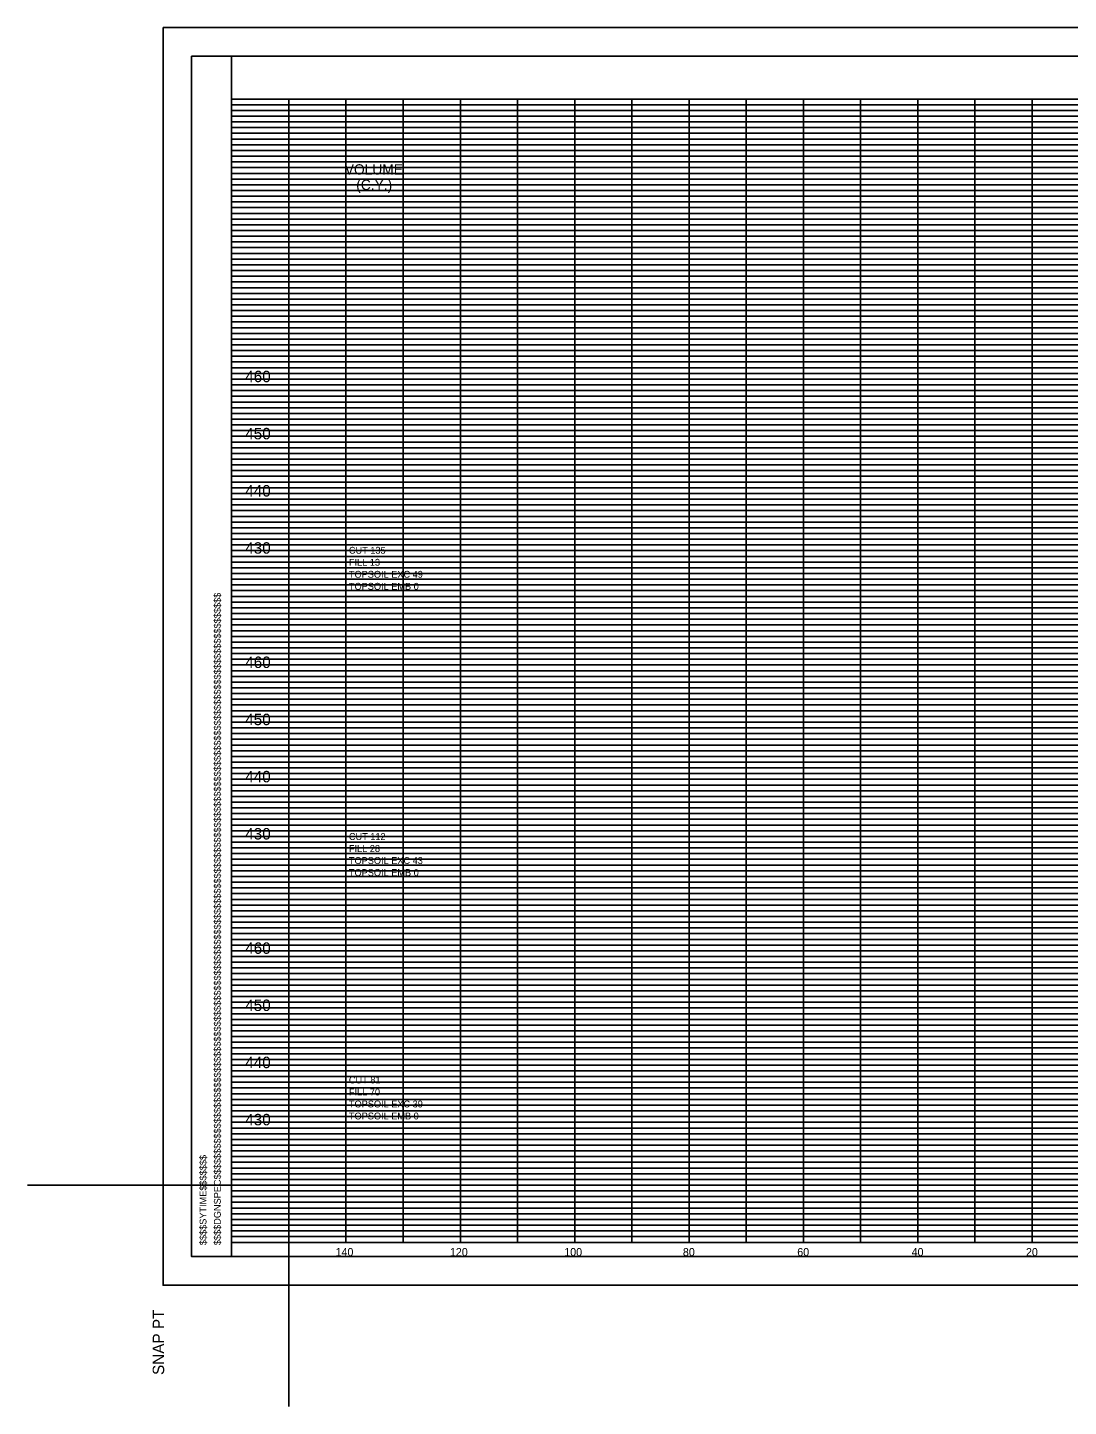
# Model space of a CAD drawing. Extents: x 37 to 1710, y 707 to 2305.
# Drawn here: x 1344.3 to 1526.3, y 971.3 to 1212.5 of the extents above; entities that cross this region are included whole.
import ezdxf

# ---------------------------------------------------------------- set-up
doc = ezdxf.new("R2010")
doc.units = 0
for name, color, linetype in [('DESIGN - SCRATCH - User 1', 7, 'Continuous'), ('DESIGN - SHEET - Corner Text', 7, 'Continuous'), ('DESIGN - SHEET - Light Grid', 7, 'Continuous'), ('DESIGN - SHEET - Linework', 7, 'Continuous'), ('DESIGN - SHEET - Plot Shape', 7, 'Continuous'), ('DESIGN - TYPICAL - Text', 7, 'Continuous')]:
    doc.layers.add(name, color=color, linetype=linetype)

msp = doc.modelspace()

# ---------------------------------------------------------------- linework, layer by layer
at = {"layer": 'DESIGN - SCRATCH - User 1'}
for p, q in [((1390, 1010), (1344.31, 1010)), ((1390, 1010), (1390, 971.3)), ((1380, 1000), (1380, 1000))]:
    msp.add_line(p, q, dxfattribs=at)
at = {"layer": 'DESIGN - SHEET - Light Grid'}
for p, q in [((1380, 1199), (1660, 1199)), ((1380, 1198), (1660, 1198)), ((1380, 1197), (1660, 1197)), ((1380, 1196), (1660, 1196)), ((1380, 1195), (1660, 1195)), ((1380, 1194), (1660, 1194)), ((1380, 1193), (1660, 1193)), ((1380, 1192), (1660, 1192)), ((1380, 1191), (1660, 1191)), ((1380, 1189), (1700, 1189)), ((1380, 1188), (1700, 1188)), ((1380, 1187), (1700, 1187)), ((1380, 1186), (1700, 1186)), ((1380, 1185), (1700, 1185)), ((1380, 1184), (1700, 1184)), ((1380, 1183), (1700, 1183)), ((1380, 1182), (1700, 1182)), ((1380, 1181), (1700, 1181)), ((1380, 1179), (1700, 1179)), ((1380, 1178), (1700, 1178)), ((1380, 1177), (1700, 1177)), ((1380, 1176), (1700, 1176)), ((1380, 1175), (1700, 1175)), ((1380, 1174), (1700, 1174)), ((1380, 1173), (1700, 1173)), ((1380, 1172), (1700, 1172)), ((1380, 1171), (1700, 1171)), ((1380, 1169), (1700, 1169)), ((1380, 1168), (1700, 1168)), ((1380, 1167), (1700, 1167)), ((1380, 1166), (1700, 1166)), ((1380, 1165), (1700, 1165)), ((1380, 1164), (1700, 1164)), ((1380, 1163), (1700, 1163)), ((1380, 1162), (1700, 1162)), ((1380, 1161), (1700, 1161)), ((1380, 1159), (1700, 1159)), ((1380, 1158), (1700, 1158)), ((1380, 1157), (1700, 1157)), ((1380, 1156), (1700, 1156)), ((1380, 1155), (1700, 1155)), ((1380, 1154), (1700, 1154)), ((1380, 1153), (1700, 1153)), ((1380, 1152), (1700, 1152)), ((1380, 1151), (1700, 1151)), ((1380, 1149), (1700, 1149)), ((1380, 1148), (1700, 1148)), ((1380, 1147), (1700, 1147)), ((1380, 1146), (1700, 1146)), ((1380, 1145), (1700, 1145)), ((1380, 1144), (1700, 1144)), ((1380, 1143), (1700, 1143)), ((1380, 1142), (1700, 1142)), ((1380, 1141), (1700, 1141)), ((1380, 1139), (1700, 1139)), ((1380, 1138), (1700, 1138)), ((1380, 1137), (1700, 1137)), ((1380, 1136), (1700, 1136)), ((1380, 1135), (1700, 1135)), ((1380, 1134), (1700, 1134)), ((1380, 1133), (1700, 1133)), ((1380, 1132), (1700, 1132)), ((1380, 1131), (1700, 1131)), ((1380, 1129), (1700, 1129)), ((1380, 1128), (1700, 1128)), ((1380, 1127), (1700, 1127)), ((1380, 1126), (1700, 1126)), ((1380, 1125), (1700, 1125)), ((1380, 1124), (1700, 1124)), ((1380, 1123), (1700, 1123)), ((1380, 1122), (1700, 1122)), ((1380, 1121), (1700, 1121)), ((1380, 1119), (1700, 1119)), ((1380, 1118), (1700, 1118)), ((1380, 1117), (1700, 1117)), ((1380, 1116), (1700, 1116)), ((1380, 1115), (1700, 1115)), ((1380, 1114), (1700, 1114)), ((1380, 1113), (1700, 1113)), ((1380, 1112), (1700, 1112)), ((1380, 1111), (1700, 1111)), ((1380, 1109), (1700, 1109)), ((1380, 1108), (1700, 1108)), ((1380, 1107), (1700, 1107)), ((1380, 1106), (1700, 1106)), ((1380, 1105), (1700, 1105)), ((1380, 1104), (1700, 1104)), ((1380, 1103), (1700, 1103)), ((1380, 1102), (1700, 1102)), ((1380, 1101), (1700, 1101)), ((1380, 1099), (1700, 1099)), ((1380, 1098), (1700, 1098)), ((1380, 1097), (1700, 1097)), ((1380, 1096), (1700, 1096)), ((1380, 1095), (1700, 1095)), ((1380, 1094), (1700, 1094)), ((1380, 1093), (1700, 1093)), ((1380, 1092), (1700, 1092)), ((1380, 1091), (1700, 1091)), ((1380, 1089), (1700, 1089)), ((1380, 1088), (1700, 1088)), ((1380, 1087), (1700, 1087)), ((1380, 1086), (1700, 1086)), ((1380, 1085), (1700, 1085)), ((1380, 1084), (1700, 1084)), ((1380, 1083), (1700, 1083)), ((1380, 1082), (1700, 1082)), ((1380, 1081), (1700, 1081)), ((1380, 1079), (1700, 1079)), ((1380, 1078), (1700, 1078)), ((1380, 1077), (1700, 1077)), ((1380, 1076), (1700, 1076)), ((1380, 1075), (1700, 1075)), ((1380, 1074), (1700, 1074)), ((1380, 1073), (1700, 1073)), ((1380, 1072), (1700, 1072)), ((1380, 1071), (1700, 1071)), ((1380, 1069), (1700, 1069)), ((1380, 1068), (1700, 1068)), ((1380, 1067), (1700, 1067)), ((1380, 1066), (1700, 1066)), ((1380, 1065), (1700, 1065)), ((1380, 1064), (1700, 1064)), ((1380, 1063), (1700, 1063)), ((1380, 1062), (1700, 1062)), ((1380, 1061), (1700, 1061)), ((1380, 1059), (1700, 1059)), ((1380, 1058), (1700, 1058)), ((1380, 1057), (1700, 1057)), ((1380, 1056), (1700, 1056)), ((1380, 1055), (1700, 1055)), ((1380, 1054), (1700, 1054)), ((1380, 1053), (1700, 1053)), ((1380, 1052), (1700, 1052)), ((1380, 1051), (1700, 1051)), ((1380, 1049), (1700, 1049)), ((1380, 1048), (1700, 1048)), ((1380, 1047), (1700, 1047)), ((1380, 1046), (1700, 1046)), ((1380, 1045), (1700, 1045)), ((1380, 1044), (1700, 1044)), ((1380, 1043), (1700, 1043)), ((1380, 1042), (1700, 1042)), ((1380, 1041), (1700, 1041)), ((1380, 1039), (1700, 1039)), ((1380, 1038), (1700, 1038)), ((1380, 1037), (1700, 1037)), ((1380, 1036), (1700, 1036)), ((1380, 1035), (1700, 1035)), ((1380, 1034), (1700, 1034)), ((1380, 1033), (1700, 1033)), ((1380, 1032), (1700, 1032)), ((1380, 1031), (1700, 1031)), ((1380, 1029), (1700, 1029)), ((1380, 1028), (1700, 1028)), ((1380, 1027), (1700, 1027)), ((1380, 1026), (1700, 1026)), ((1380, 1025), (1700, 1025)), ((1380, 1024), (1700, 1024)), ((1380, 1023), (1700, 1023)), ((1380, 1022), (1700, 1022)), ((1380, 1021), (1700, 1021)), ((1380, 1019), (1700, 1019)), ((1380, 1018), (1700, 1018)), ((1380, 1017), (1700, 1017)), ((1380, 1016), (1700, 1016)), ((1380, 1015), (1700, 1015)), ((1380, 1014), (1700, 1014)), ((1380, 1013), (1700, 1013)), ((1380, 1012), (1700, 1012)), ((1380, 1011), (1700, 1011)), ((1380, 1009), (1700, 1009)), ((1380, 1008), (1700, 1008)), ((1380, 1007), (1700, 1007)), ((1380, 1006), (1700, 1006)), ((1380, 1005), (1700, 1005)), ((1380, 1004), (1700, 1004)), ((1380, 1003), (1700, 1003)), ((1380, 1002), (1700, 1002)), ((1380, 1001), (1700, 1001))]:
    msp.add_line(p, q, dxfattribs=at)
at = {"layer": 'DESIGN - SHEET - Linework'}
for p, q in [((1380, 1200), (1700, 1200)), ((1390, 1000), (1390, 1200)), ((1400, 1000), (1400, 1200)), ((1410, 1000), (1410, 1200)), ((1420, 1000), (1420, 1200)), ((1430, 1000), (1430, 1200)), ((1440, 1000), (1440, 1200)), ((1450, 1000), (1450, 1200)), ((1460, 1000), (1460, 1200)), ((1470, 1000), (1470, 1200)), ((1480, 1000), (1480, 1200)), ((1490, 1000), (1490, 1200)), ((1500, 1000), (1500, 1200)), ((1510, 1000), (1510, 1200)), ((1520, 1000), (1520, 1200)), ((1380, 1190), (1700, 1190)), ((1380, 1180), (1700, 1180)), ((1380, 1170), (1700, 1170)), ((1380, 1160), (1700, 1160)), ((1380, 1150), (1700, 1150)), ((1380, 1140), (1700, 1140)), ((1380, 1130), (1700, 1130)), ((1380, 1120), (1700, 1120)), ((1380, 1110), (1700, 1110)), ((1380, 1100), (1700, 1100)), ((1380, 1090), (1700, 1090)), ((1380, 1080), (1700, 1080)), ((1380, 1070), (1700, 1070)), ((1380, 1060), (1700, 1060)), ((1380, 1050), (1700, 1050)), ((1380, 1040), (1700, 1040)), ((1380, 1030), (1700, 1030)), ((1380, 1020), (1700, 1020)), ((1380, 1010), (1700, 1010)), ((1380, 1000), (1700, 1000))]:
    msp.add_line(p, q, dxfattribs=at)
for points in [[(1368, 1212.5), (1708, 1212.5), (1708, 992.5), (1368, 992.5)], [(1380, 1207.5), (1700, 1207.5), (1700, 997.5), (1380, 997.5)]]:
    msp.add_lwpolyline(points, close=True, dxfattribs=at)
at = {"layer": 'DESIGN - SHEET - Plot Shape'}
msp.add_lwpolyline([(1373, 1207.5), (1703, 1207.5), (1703, 997.5), (1373, 997.5)], close=True, dxfattribs=at)

# ---------------------------------------------------------------- texts
at = {"layer": 'DESIGN - SHEET - Corner Text'}
for s, height, p in [('$$$$DGNSPEC$$$$$$$$$$$$$$$$$$$$$$$$$$$$$$$$$$$$$$$$$$$$$$$$$$$$$$$$$$$$$$$$$$$$$$$$$$$$$$$$$$$$$$$$$$$$$$$$$$$$$$$$$$$$$$$$$$$', 1.2, (1378.1, 999.5)), ('$$$$SYTIME$$$$$$$', 1.2, (1375.6, 999.5)), ('SNAP PT  ', 2, (1368.2, 976.8))]:
    msp.add_text(s, height=height, rotation=90, dxfattribs=at).set_placement(p)
for s, p in [('     450     ', (1378.66, 1090.47)), ('     440     ', (1378.66, 1080.47)), ('     430     ', (1378.66, 1070.47)), ('     460     ', (1378.66, 1050.47)), ('     450     ', (1378.66, 1040.47))]:
    msp.add_text(s, height=2, dxfattribs=at).set_placement(p)
at = {"layer": 'DESIGN - TYPICAL - Text'}
for s, height, p in [('VOLUME', 1.8, (1399.79, 1186.79)), ('   (C.Y.)', 1.8, (1399.79, 1184.09)), ('     460     ', 2, (1378.66, 1150.47)), ('     450     ', 2, (1378.66, 1140.47)), ('     440     ', 2, (1378.66, 1130.47)), ('     430     ', 2, (1378.66, 1120.47)), ('CUT 135', 1.2, (1400.51, 1120.46)), ('FILL 13', 1.2, (1400.51, 1118.36)), ('TOPSOIL EXC 49', 1.2, (1400.51, 1116.26)), ('TOPSOIL EMB 0', 1.2, (1400.51, 1114.16)), ('     460     ', 2, (1378.66, 1100.47)), ('CUT 112', 1.2, (1400.51, 1070.39)), ('FILL 28', 1.2, (1400.51, 1068.29)), ('TOPSOIL EXC 43', 1.2, (1400.51, 1066.19)), ('TOPSOIL EMB 0', 1.2, (1400.51, 1064.09)), ('     440     ', 2, (1378.66, 1030.47)), ('CUT 81', 1.2, (1400.51, 1027.8)), ('FILL 70', 1.2, (1400.51, 1025.7)), ('TOPSOIL EXC 39', 1.2, (1400.51, 1023.6)), ('TOPSOIL EMB 0', 1.2, (1400.51, 1021.5)), ('     430     ', 2, (1378.66, 1020.47)), ('     140     ', 1.4, (1395.57, 997.6)), ('     120     ', 1.4, (1415.57, 997.6)), ('     100     ', 1.4, (1435.57, 997.6)), ('     80     ', 1.4, (1456.32, 997.6)), ('     60     ', 1.4, (1476.32, 997.6)), ('     40     ', 1.4, (1496.32, 997.6)), ('     20     ', 1.4, (1516.32, 997.6))]:
    msp.add_text(s, height=height, dxfattribs=at).set_placement(p)

doc.saveas('drawing.dxf')
